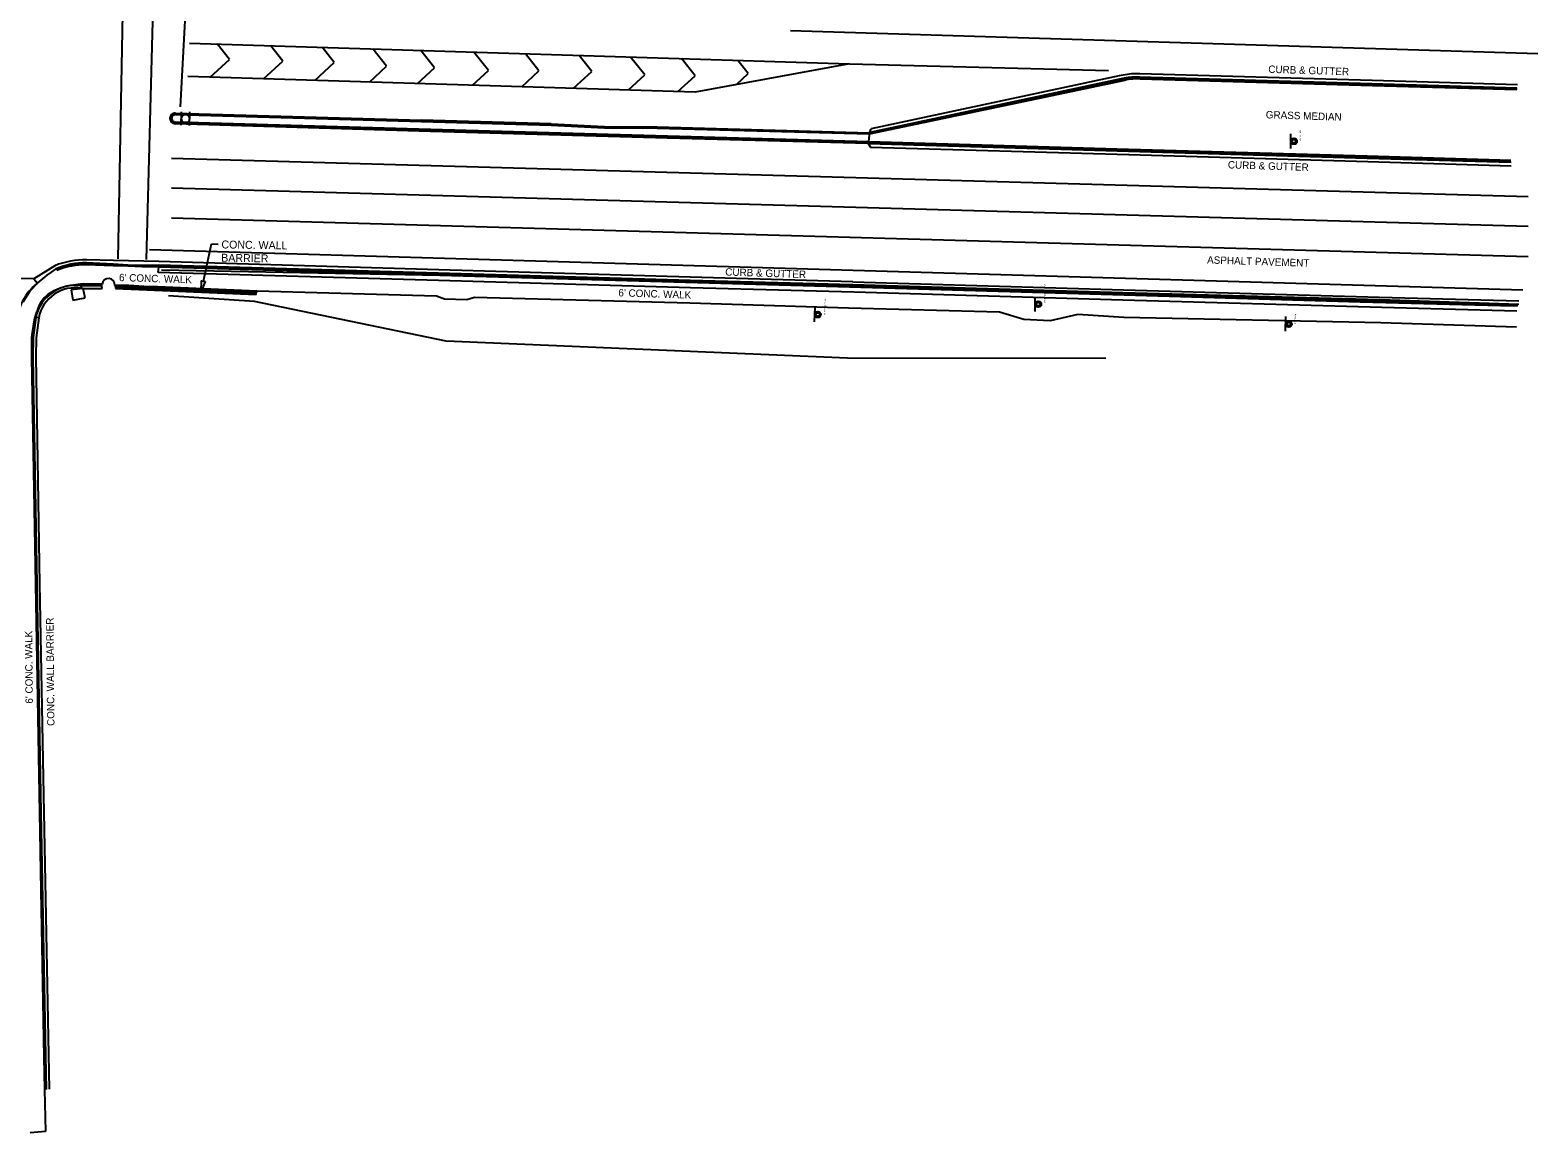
# Model space of a CAD drawing. Extents: x 925226 to 926411, y 852913 to 858733.
# Drawn here: x 925841 to 926411, y 853170 to 853587 of the extents above; entities that cross this region are included whole.
import ezdxf

# ---------------------------------------------------------------- set-up
doc = ezdxf.new("R2010")
doc.units = 0
for name, color, linetype in [('BankMent_ep', 7, 'Continuous'), ('CGep_ep', 7, 'Continuous'), ('CGFace_ep', 7, 'Continuous'), ('CLConst_dp', 7, 'Continuous'), ('ConcSlabs_ep', 7, 'Continuous'), ('DelineatorPost_ep', 7, 'Continuous'), ('EndTreat_ep', 7, 'Continuous'), ('GuardrailRt_ep', 7, 'Continuous'), ('LaneLine_ep', 7, 'Continuous'), ('ManholeSW_ep', 7, 'Continuous'), ('PavtAsphalt_ep', 7, 'Continuous'), ('PavtConcrete_ep', 7, 'Continuous'), ('PavtMisc_ep', 7, 'Continuous'), ('SidewalkBack_ep', 7, 'Continuous'), ('SidewalkFront_ep', 7, 'Continuous'), ('TextLabel', 7, 'Continuous'), ('WallBarrier_ep', 7, 'Continuous'), ('XSPt_ep', 7, 'Continuous')]:
    doc.layers.add(name, color=color, linetype=linetype)

# ---------------------------------------------------------------- blocks, each defined once
blk = doc.blocks.new('SSS')
at = {"layer": 'ManholeSW_ep'}
blk.add_line((-2.77, 1.15), (2.77, 1.15), dxfattribs=at)
for radius in [1.15, 0.692]:
    blk.add_circle((0, 0), radius, dxfattribs=at)
blk = doc.blocks.new('DLP')
at = {"layer": 'DelineatorPost_ep'}
for p, q in [((-1.54, -2.57), (-1.54, 2.57)), ((1.54, -2.57), (1.54, 2.57))]:
    blk.add_line(p, q, dxfattribs=at)
blk.add_circle((0, 0), 1.54, dxfattribs=at)

msp = doc.modelspace()

# ---------------------------------------------------------------- linework, layer by layer
at = {"layer": 'BankMent_ep'}
for p, q in [((925925.89, 853484.67), (925893.37, 853486.76)), ((925998.38, 853469.67), (925925.89, 853484.67)), ((926150.19, 853463.15), (925998.38, 853469.67)), ((926247.86, 853463.06), (926150.19, 853463.15))]:
    msp.add_line(p, q, dxfattribs=at)
at = {"layer": 'CGep_ep'}
for p, q in [((926254.78, 853569.1), (926158.59, 853548.52)), ((926348.47, 853566.96), (926260.57, 853569.44)), ((926403.31, 853565.28), (926348.47, 853566.96)), ((926256.39, 853541.36), (926158.17, 853544.25)), ((926346.68, 853538.75), (926256.39, 853541.36)), ((926401.08, 853537.23), (926346.68, 853538.75)), ((925872.4, 853498.79), (925862.35, 853499.24)), ((925878.03, 853498.3), (925872.4, 853498.79)), ((925883.43, 853498.2), (925878.03, 853498.3)), ((925889.71, 853498.39), (925883.43, 853498.2)), ((925995.36, 853495.3), (925889.71, 853498.39)), ((925850.78, 853496.95), (925848.1, 853495.08)), ((926090.6, 853492.56), (925995.36, 853495.3)), ((926152.11, 853490.88), (926090.6, 853492.56)), ((926254.29, 853487.95), (926152.11, 853490.88)), ((926351.39, 853485.2), (926254.29, 853487.95)), ((926403.95, 853483.54), (926351.39, 853485.2))]:
    msp.add_line(p, q, dxfattribs=at)
for centre, major_axis, ratio, start_param, end_param in [((926259.73, 853534.56), (33.53, 9.65), 0.999963, 1.266367, 1.432867), ((925861.75, 853472.07), (27.25, 0.39), 0.996973, 1.534694, 1.970943)]:
    msp.add_ellipse(centre, major_axis=major_axis, ratio=ratio, start_param=start_param, end_param=end_param, dxfattribs=at)
at = {"layer": 'CGFace_ep'}
for p, q in [((926254.82, 853568.76), (926158.46, 853548.16)), ((926348.6, 853566.56), (926260.61, 853569.15)), ((926403.37, 853565), (926348.6, 853566.56)), ((925989.07, 853553.03), (925896.04, 853555.76)), ((925896.01, 853551.96), (925987.9, 853549.33)), ((925987.9, 853549.33), (926082.08, 853546.59)), ((926038.08, 853551.59), (925989.07, 853553.03)), ((926058.2, 853550.67), (926038.08, 853551.59)), ((926078.2, 853550.48), (926058.2, 853550.67)), ((926158.46, 853548.16), (926078.2, 853550.48)), ((926082.08, 853546.59), (926158.15, 853544.56)), ((926158.15, 853544.56), (926256.34, 853541.66)), ((926256.34, 853541.66), (926346.62, 853539.06)), ((926346.62, 853539.06), (926401.04, 853537.57)), ((925872.34, 853498.57), (925862.4, 853498.89)), ((925872.34, 853498.57), (925878.03, 853498.3)), ((925883.43, 853498.2), (925889.6, 853498.03)), ((925995.43, 853495.06), (925889.6, 853498.03)), ((926090.55, 853492.34), (925995.43, 853495.06)), ((926152.14, 853490.48), (926090.55, 853492.34)), ((926254.36, 853487.63), (926152.14, 853490.48)), ((926351.39, 853484.86), (926254.36, 853487.63)), ((926403.66, 853483.28), (926351.39, 853484.86))]:
    msp.add_line(p, q, dxfattribs=at)
for centre, major_axis, ratio, start_param, end_param in [((926259.25, 853546.47), (19, 12.46), 0.999986, 0.930803, 1.186749), ((925861.17, 853474.48), (24.52, 0.73), 0.996312, 1.490706, 1.973934)]:
    msp.add_ellipse(centre, major_axis=major_axis, ratio=ratio, start_param=start_param, end_param=end_param, dxfattribs=at)
at = {"layer": 'ConcSlabs_ep'}
for p, q in [((926158.34, 853547.69), (926158.06, 853545.05)), ((925861.12, 853489.55), (925856.56, 853489.01)), ((925856.56, 853489.01), (925857.14, 853485.1)), ((925861.87, 853485.97), (925861.12, 853489.55)), ((925857.14, 853485.1), (925861.87, 853485.97))]:
    msp.add_line(p, q, dxfattribs=at)
at = {"layer": 'EndTreat_ep'}
for p, q in [((925874.28, 853500.75), (925877.09, 853647.61)), ((925888.87, 853646.07), (925884.89, 853500.54)), ((925897.87, 853558.21), (925902.53, 853645.16)), ((925901.28, 853582.35), (926150.91, 853574.44)), ((925916.39, 853576.14), (925911.74, 853582.02)), ((925936.61, 853575.52), (925931.98, 853581.38)), ((925956.01, 853574.98), (925951.43, 853580.76)), ((925975.81, 853573.55), (925970.58, 853580.15)), ((925993.99, 853572.98), (925988.77, 853579.58)), ((926014.37, 853571.98), (926008.86, 853578.94)), ((926033.47, 853571.84), (926028.34, 853578.32)), ((926053.44, 853571.62), (926048.65, 853577.68)), ((925909.08, 853569.41), (925916.39, 853576.14)), ((925929.3, 853568.8), (925936.61, 853575.52)), ((925948.66, 853568.21), (925956.01, 853574.98)), ((925969.33, 853567.58), (925975.81, 853573.55)), ((925987.52, 853567.02), (925993.99, 853572.98)), ((926008.3, 853566.39), (926014.37, 853571.98)), ((926073.47, 853570.27), (926068.09, 853577.06)), ((926092.49, 853569.98), (926087.37, 853576.45)), ((926150.91, 853574.44), (926092.52, 853563.82)), ((926112.6, 853570.77), (926108.63, 853575.78)), ((926150.91, 853574.44), (926248.8, 853571.9)), ((926092.52, 853563.82), (925900.71, 853569.67)), ((926026.94, 853565.82), (926033.47, 853571.84)), ((926046.49, 853565.22), (926053.44, 853571.62)), ((926067.3, 853564.59), (926073.47, 853570.27)), ((926086.01, 853564.02), (926092.49, 853569.98)), ((926108.13, 853566.66), (926112.6, 853570.77)), ((925886.24, 853504.27), (926405.56, 853489.06))]:
    msp.add_line(p, q, dxfattribs=at)
at = {"layer": 'GuardrailRt_ep'}
for p, q in [((925890.71, 853496.64), (925995.92, 853494.57)), ((925995.92, 853494.57), (926150.84, 853490.19)), ((926150.84, 853490.19), (926254.77, 853487.1)), ((926254.77, 853487.1), (926343.95, 853484.53)), ((926343.95, 853484.53), (926401.81, 853482.96))]:
    msp.add_line(p, q, dxfattribs=at)
at = {"layer": 'LaneLine_ep'}
for p, q in [((926128.6, 853587.04), (926411.2, 853578.4)), ((925894.47, 853538.79), (926407.53, 853524.29)), ((925894.47, 853527.64), (926407.53, 853513.13)), ((925894.47, 853516.2), (926407.53, 853501.7))]:
    msp.add_line(p, q, dxfattribs=at)
at = {"layer": 'PavtAsphalt_ep'}
for p, q in [((926252.88, 853569.88), (926159.14, 853549.95)), ((926257.59, 853570.67), (926252.88, 853569.88)), ((926260.65, 853570.64), (926257.59, 853570.67)), ((926348.54, 853568.15), (926260.65, 853570.64)), ((926403.46, 853566.54), (926348.54, 853568.15)), ((925896.05, 853555.89), (925989.04, 853553.24)), ((925988.02, 853549.07), (925896.03, 853551.83)), ((926038.07, 853551.77), (925989.04, 853553.24)), ((926038.07, 853551.77), (926058.13, 853550.81)), ((926058.13, 853550.81), (926078.17, 853550.64)), ((926078.17, 853550.64), (926158.44, 853548.34)), ((926158.44, 853548.34), (926159.14, 853549.95)), ((926081.97, 853546.42), (925988.02, 853549.07)), ((926157.98, 853544.32), (926081.97, 853546.42)), ((926157.98, 853544.32), (926158.89, 853542.94)), ((926158.89, 853542.94), (926256.47, 853540.16)), ((926256.47, 853540.16), (926346.87, 853537.56)), ((926346.87, 853537.56), (926401.05, 853535.94)), ((925850.36, 853498.15), (925842.5, 853493.23)), ((925872.51, 853500.12), (925862.42, 853500.41)), ((925889.66, 853499.69), (925872.51, 853500.12)), ((925995.55, 853496.64), (925889.66, 853499.69)), ((925842.5, 853493.23), (925824.99, 853493.51)), ((925842.5, 853493.23), (925843.88, 853491.61)), ((926090.59, 853493.77), (925995.55, 853496.64)), ((926152.13, 853492.05), (926090.59, 853493.77)), ((926152.13, 853492.05), (926254.5, 853489.1)), ((926254.5, 853489.1), (926351.37, 853486.26)), ((926351.37, 853486.26), (926403.95, 853484.83))]:
    msp.add_line(p, q, dxfattribs=at)
for centre, major_axis, ratio, start_param, end_param in [((925895.95, 853553.86), (1.93, 0.64), 0.99922, 1.205345, 4.42952), ((925862.36, 853467.57), (32.81, 2.98), 0.997, 1.478444, 1.852998)]:
    msp.add_ellipse(centre, major_axis=major_axis, ratio=ratio, start_param=start_param, end_param=end_param, dxfattribs=at)
at = {"layer": 'PavtConcrete_ep'}
msp.add_ellipse((925856.96, 853474.93), major_axis=(-11.32, -17.95), ratio=0.998932, start_param=4.369426, end_param=5.21253, dxfattribs=at)
at = {"layer": 'PavtMisc_ep'}
for p, q in [((925889.47, 853495.57), (925889.67, 853497.59)), ((925995.51, 853492.52), (925889.47, 853495.57)), ((926090.77, 853489.8), (925995.51, 853492.52)), ((926152.61, 853488.15), (926090.77, 853489.8)), ((926254.32, 853485.1), (926152.61, 853488.15)), ((926352.24, 853482.4), (926254.32, 853485.1)), ((926403.3, 853480.91), (926352.24, 853482.4))]:
    msp.add_line(p, q, dxfattribs=at)
at = {"layer": 'SidewalkBack_ep'}
for p, q in [((925860.05, 853491.18), (925857.42, 853490.82)), ((925861.1, 853491.26), (925860.05, 853491.18)), ((925868.24, 853491.16), (925861.1, 853491.26)), ((925878.41, 853490.64), (925873.1, 853490.73)), ((925884.01, 853490.32), (925878.41, 853490.64)), ((925889.21, 853490.2), (925884.01, 853490.32)), ((925926.78, 853488.51), (925889.21, 853490.2)), ((925994.76, 853486.59), (925926.78, 853488.51)), ((925997.79, 853485.47), (925994.76, 853486.59)), ((926006.21, 853485.26), (925997.79, 853485.47)), ((926009.08, 853486.19), (926006.21, 853485.26)), ((926090.5, 853483.94), (926009.08, 853486.19)), ((926150.46, 853482.13), (926090.5, 853483.94)), ((926207.62, 853480.57), (926150.46, 853482.13)), ((925841.96, 853472.91), (925842.65, 853477.68)), ((925842.65, 853477.68), (925843.61, 853480.66)), ((926216.8, 853477.77), (926207.62, 853480.57)), ((926226.83, 853477.3), (926216.8, 853477.77)), ((926237.19, 853479.77), (926226.83, 853477.3)), ((926254.61, 853478.6), (926237.19, 853479.77)), ((926351.8, 853476.6), (926254.61, 853478.6)), ((926403.07, 853474.94), (926351.8, 853476.6)), ((925841.63, 853469.14), (925841.71, 853471)), ((925841.71, 853471), (925841.96, 853472.91)), ((925841.63, 853469.14), (925841.65, 853463.69)), ((925841.65, 853463.69), (925843.1, 853377.85)), ((925843.1, 853377.85), (925844.6, 853291.4)), ((925844.6, 853291.4), (925845.13, 853261.9)), ((925845.13, 853261.9), (925846.27, 853198.89)), ((925846.27, 853198.89), (925846.52, 853186.72)), ((925846.52, 853186.72), (925846.89, 853170.87)), ((925846.89, 853170.87), (925841.05, 853170.33))]:
    msp.add_line(p, q, dxfattribs=at)
for centre, major_axis, ratio, start_param, end_param in [((925870.67, 853490.92), (1.64, 1.81), 0.999772, 5.372118, 8.492683), ((925854.68, 853478.47), (8.12, 8.16), 0.97187, 1.44226, 2.146102), ((925859.25, 853470.93), (-11.67, 16.22), 0.998018, 5.750578, 6.266098)]:
    msp.add_ellipse(centre, major_axis=major_axis, ratio=ratio, start_param=start_param, end_param=end_param, dxfattribs=at)
at = {"layer": 'SidewalkFront_ep'}
for p, q in [((925843.89, 853491.55), (925848.1, 853495.08)), ((925838.43, 853484.52), (925841.05, 853488.64)), ((925841.05, 853488.64), (925843.89, 853491.55))]:
    msp.add_line(p, q, dxfattribs=at)
at = {"layer": 'TextLabel'}
for points in [[(925906.56, 853492.28), (925909.57, 853506.37)], [(925909.57, 853506.37), (925912.11, 853506.33)]]:
    msp.add_lwpolyline(points, dxfattribs=at)
msp.add_lwpolyline([(925907.21, 853492.14), (925905.72, 853488.36), (925905.91, 853492.41)], close=True, dxfattribs=at)
at = {"layer": 'WallBarrier_ep'}
for p, q in [((925868.22, 853491.02), (925860.05, 853491.18)), ((925860.05, 853491.18), (925860.07, 853490.71)), ((925860.07, 853490.71), (925860.13, 853490.6)), ((925868.2, 853490.63), (925860.07, 853490.71)), ((925860.13, 853490.6), (925860.54, 853489.59)), ((925868.22, 853490.4), (925860.13, 853490.6)), ((925860.54, 853489.59), (925868.23, 853489.6)), ((925868.2, 853490.63), (925868.22, 853491.02)), ((925868.22, 853490.4), (925868.2, 853490.63)), ((925868.23, 853489.6), (925868.22, 853490.4)), ((925873.33, 853490.32), (925873.36, 853490.72)), ((925926.53, 853488.05), (925873.33, 853490.32)), ((925873.33, 853490.32), (925873.35, 853490.08)), ((925873.35, 853490.08), (925873.34, 853489.55)), ((925873.34, 853489.55), (925926.56, 853487.32)), ((925926.58, 853487.81), (925873.35, 853490.08)), ((925873.36, 853490.72), (925926.66, 853488.45)), ((925926.66, 853488.45), (925926.53, 853488.05)), ((925926.58, 853487.81), (925926.53, 853488.05)), ((925926.56, 853487.32), (925926.58, 853487.81)), ((925843.21, 853478.64), (925842.2, 853471.05)), ((925844.29, 853478.5), (925843.21, 853478.64)), ((925844.29, 853478.5), (925843.29, 853470.92)), ((925841.71, 853463.44), (925841.74, 853470.91)), ((925842.18, 853470.9), (925842.04, 853463.48)), ((925842.2, 853463.38), (925842.2, 853471.05)), ((925843.29, 853470.92), (925843.15, 853463.54)), ((925843.17, 853377.81), (925841.71, 853463.44)), ((925842.04, 853463.48), (925843.55, 853377.9)), ((925843.69, 853377.79), (925842.2, 853463.38)), ((925843.15, 853463.54), (925844.58, 853377.84)), ((925844.67, 853291.35), (925843.17, 853377.81)), ((925843.55, 853377.9), (925845.14, 853291.39)), ((925845.24, 853291.35), (925843.69, 853377.79)), ((925844.58, 853377.84), (925846.17, 853291.39)), ((925846.61, 853186.79), (925844.67, 853291.35)), ((925845.14, 853291.39), (925846.96, 853186.74)), ((925847.28, 853186.76), (925845.24, 853291.35)), ((925846.17, 853291.39), (925848.18, 853186.89))]:
    msp.add_line(p, q, dxfattribs=at)
for centre, major_axis, ratio, start_param, end_param in [((925858.11, 853475.47), (-7.73, -13.17), 0.997297, 3.540414, 5.032834), ((925858.01, 853475.81), (-7.94, -11.56), 0.996498, 3.563221, 5.118928)]:
    msp.add_ellipse(centre, major_axis=major_axis, ratio=ratio, start_param=start_param, end_param=end_param, dxfattribs=at)
at = {"layer": 'XSPt_ep'}
for p, q in [((926254.98, 853568.2), (926158.3, 853547.85)), ((926348.63, 853566.12), (926260.82, 853568.7)), ((926403.29, 853564.6), (926348.63, 853566.12)), ((925989.08, 853552.58), (925896.08, 853555.22)), ((925988.01, 853549.72), (925895.94, 853552.47)), ((926082.07, 853547.08), (925988.01, 853549.72)), ((926038.08, 853551.15), (925989.08, 853552.58)), ((926058.23, 853550.18), (926038.08, 853551.15)), ((926078.16, 853550.04), (926058.23, 853550.18)), ((926158.3, 853547.85), (926078.16, 853550.04)), ((926158.16, 853545.02), (926082.07, 853547.08)), ((926256.44, 853542.15), (926158.16, 853545.02)), ((926346.67, 853539.59), (926256.44, 853542.15)), ((926400.99, 853537.94), (926346.67, 853539.59)), ((925872.46, 853498.08), (925862.39, 853498.46)), ((925877.95, 853497.99), (925872.46, 853498.08)), ((925883.36, 853497.76), (925877.95, 853497.99)), ((925889.67, 853497.59), (925883.36, 853497.76)), ((925995.39, 853494.64), (925889.67, 853497.59)), ((926152.16, 853490.08), (925995.39, 853494.64)), ((926254.2, 853487.2), (926152.16, 853490.08)), ((926351.66, 853484.35), (926254.2, 853487.2)), ((926403.48, 853482.88), (926351.66, 853484.35))]:
    msp.add_line(p, q, dxfattribs=at)
for centre, major_axis, ratio, start_param, end_param in [((926259.35, 853551.51), (-17.32, -0.48), 0.996085, 4.600145, 4.940393), ((925895.97, 853553.86), (1.82, -0.55), 0.998267, 1.830122, 5.025123), ((925895.94, 853553.85), (1.35, 0.29), 0.998667, 1.255158, 4.495042), ((925861.58, 853471.86), (26.68, -1.22), 0.996676, 1.585943, 2.019368)]:
    msp.add_ellipse(centre, major_axis=major_axis, ratio=ratio, start_param=start_param, end_param=end_param, dxfattribs=at)

# ---------------------------------------------------------------- block references
at = {"layer": 'DelineatorPost_ep', "rotation": -1.3261543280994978}
msp.add_blockref('DLP', (925899.79, 853553.78), dxfattribs=at)
at = {"layer": 'ManholeSW_ep'}
for p, rotation in [((926318.96, 853545.22), 89.99999999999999), ((926138.9, 853479.7), 87.23392015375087), ((926222.26, 853483.62), 89.99999999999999), ((926317, 853476.11), 88.82349421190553)]:
    msp.add_blockref('SSS', p, dxfattribs=dict(at, rotation=rotation))

# ---------------------------------------------------------------- texts
at = {"layer": 'CLConst_dp'}
for s, rotation, p in [('SPEED LIMIT', 90, (926321.63, 853545.22)), ('TURNPIKE SIGN  POST', 90, (926224.93, 853483.62)), ('INTERSTATE SIGN', 87.2339, (926141.7, 853479.62)), ('SPEED LIMIT', 88.8235, (926319.73, 853476.08))]:
    msp.add_text(s, height=0.5, rotation=rotation, dxfattribs=at).set_placement(p)
at = {"layer": 'TextLabel'}
for s, height, rotation, p in [('CURB & GUTTER', 2.8, 358.1724, (926309.23, 853571.09)), ('GRASS MEDIAN', 2.8, 358.1724, (926308.28, 853553.89)), ('CURB & GUTTER', 2.8, 358.1724, (926293.95, 853534.96)), ('CONC. WALL', 3, 359.0932, (925913.37, 853504.71)), ('BARRIER', 3, 359.0932, (925913.29, 853499.69)), ('ASPHALT PAVEMENT', 2.8, 358.1724, (926286.09, 853499)), ("6' CONC. WALK", 2.8, 358.1724, (925874.64, 853492.35)), ('CURB & GUTTER', 2.8, 358.1724, (926103.87, 853494.45)), ("6' CONC. WALK", 2.8, 358.1724, (926063.45, 853486.58)), ('CONC. WALL BARRIER', 2.8, 90.5061, (925850.25, 853324.16)), ("6' CONC. WALK", 2.8, 90.5061, (925842.08, 853332.6))]:
    msp.add_text(s, height=height, rotation=rotation, dxfattribs=at).set_placement(p)

doc.saveas('drawing.dxf')
